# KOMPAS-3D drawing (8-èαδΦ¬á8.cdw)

Referenced files: Чертеж крышки.cdw
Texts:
  Крышка сквозная
  Noncommercial version
  1. Литейные уклоны- 3 , литейные радиусы- 3...5мм.
  Symbol type B
  2. Неуказанные предельные откланения размеров: h14, H14,  IT14 2 .
  Ra 3,2
  Ra 6,3
  СЧ15 ГОСТ 1412-79
  ТФ ДГТУ
Dimensions and other numbers on the sheet: 0,75; 1; 2; 85; 7; 5; 10; 25; 140; 70; 190; 0.020; 0,060; 165; 6 отв.; 1:1; 9; 0,65; 0; 3; 4; 6; 8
